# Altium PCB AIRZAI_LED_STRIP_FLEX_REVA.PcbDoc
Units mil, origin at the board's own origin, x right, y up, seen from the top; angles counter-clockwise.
Board outline 6238.19 x 814.96 mil, 2 copper layers (Top Layer, Bottom Layer); 59 components, 60 nets, 298 pads, 62 vias.
Unrouted connection lines stored in the file: 83.
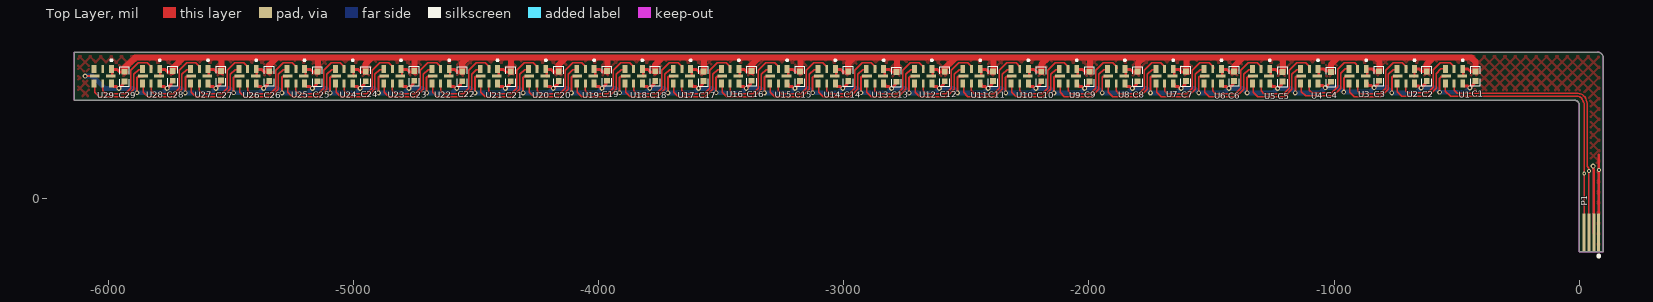
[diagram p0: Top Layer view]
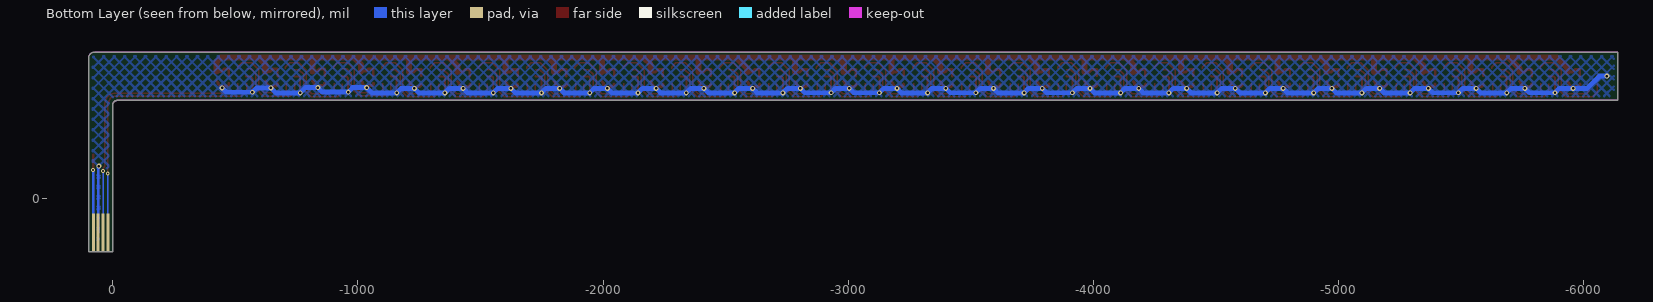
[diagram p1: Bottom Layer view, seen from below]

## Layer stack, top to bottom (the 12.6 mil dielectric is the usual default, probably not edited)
Top Solder: solder mask 0.4, Solder Resist, Dk 3.5
Top Layer: signal copper 1.4
Dielectric 1: dielectric 12.6, FR-4, Dk 4.8
Bottom Layer: signal copper 1.4
Bottom Solder: solder mask 0.4, Solder Resist, Dk 3.5

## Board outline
-6139.76,401 -6139.76,597.85 73.39,597.85 cw(c73.39,572.81) 98.43,572.81 98.43,-217.11 0,-217.11 0,381.31 ccw(c-19.69,381.31) -19.69,401
board region "Layer Stack Region 1": 98.43,43 98.43,-217.11 0,-217.11 0,43
board region "Layer Stack Region 1": 0,75 0,381.31 -0.38,385.16 -3.32,392.25 -8.75,397.68 -15.84,400.62 -19.69,401 -6139.76,401 -6139.76,597.85 73.39,597.85 78.37,597.85 87.57,594.04 94.61,586.99 98.43,577.79 98.43,572.81 98.43,75
board region "Layer Stack Region 2": 0,43 0,75 98.43,75 98.43,43

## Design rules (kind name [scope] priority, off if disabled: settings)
Clearance Clearance_polygon_5V [OnLayer('Keep-Out Layer') vs (InNet('+5V') AND InPolygon)] p1: gap=10 ignorepadtopadclearanceinfootprint=FALSE
Clearance Clearance_POLYGON_KEEPOUT [(OnLayer('Keep-Out Layer')) vs (InNet('GND') AND InPolygon)] p2: gap=10 ignorepadtopadclearanceinfootprint=FALSE
Clearance [All] p3: gap=6 ignorepadtopadclearanceinfootprint=FALSE
MinimumSolderMaskSliver [All] p1: minsoldermaskwidth=1
PolygonConnect [All] p1: connectstyle=Direct reliefconductorwidth=10 reliefentries=4 polygonreliefangle="90 Angle" airgapwidth=10
RoomDefinition AIRZAI_LED_STRIP_FLEX_REVA [InComponentClass('AIRZAI_LED_STRIP_FLEX_REVA')] p1: confinementstyle=ConfineIn formatcopy=TRUE lockcomponents=FALSE outline -10323.91,-4725.44 4336.09,-4725.44 4336.09,4874.56 -10323.91,4874.56
RoutingVias [All] p1: holewidth=28 width=50 viastyle="Through Hole" minholewidth=8 minwidth=16 maxholewidth=28 maxwidth=50
SilkToSilkClearance [All] p1: silktosilkclearance=1
SilkToSolderMaskClearance [IsPad] p1: minsilkscreentomaskgap=2 clearancetoexposedcopper=TRUE
SolderMaskExpansion [All] p1: expansion=4
UnRoutedNet [All] p1: checkbadconnections=TRUE
Width [All] p1: maxlimit=100 minlimit=6 preferedwidth=10
26 further rules are at their usual default settings.

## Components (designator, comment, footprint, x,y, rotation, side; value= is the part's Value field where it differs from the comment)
C1 "0.1µF" 0402CAP -423.76,499.43 r270 top
C2 "0.1µF" 0402CAP -622.6,499.43 r270 top
C3 "0.1µF" 0402CAP -817.46,500.11 r270 top
C4 "0.1µF" 0402CAP -1012.82,496.43 r270 top
C5 "0.1µF" 0402CAP -1210.17,497.11 r270 top
C6 "0.1µF" 0402CAP -1408.02,499.43 r270 top
C7 "0.1µF" 0402CAP -1604.87,499.11 r270 top
C8 "0.1µF" 0402CAP -1801.72,498.46 r270 top
C9 "0.1µF" 0402CAP -1997.57,497.93 r270 top
C10 "0.1µF" 0402CAP -2194.42,498.11 r270 top
C11 "0.1µF" 0402CAP -2391.59,499.11 r270 top
C12 "0.1µF" 0402CAP -2588.12,498.61 r270 top
C13 "0.1µF" 0402CAP -2784.97,496.42 r270 top
C14 "0.1µF" 0402CAP -2982.33,499.11 r270 top
C15 "0.1µF" 0402CAP -3178.76,499.11 r270 top
C16 "0.1µF" 0402CAP -3376.15,500.64 r270 top
C17 "0.1µF" 0402CAP -3572.37,499.11 r270 top
C18 "0.1µF" 0402CAP -3769.22,499.64 r270 top
C19 "0.1µF" 0402CAP -3965.64,500.58 r270 top
C20 "0.1µF" 0402CAP -4162.92,499.11 r270 top
C21 "0.1µF" 0402CAP -4358.77,498.63 r270 top
C22 "0.1µF" 0402CAP -4556.37,498.74 r270 top
C23 "0.1µF" 0402CAP -4752.47,500.58 r270 top
C24 "0.1µF" 0402CAP -4950.32,498.58 r270 top
C25 "0.1µF" 0402CAP -5146.9,498.9 r270 top
C26 "0.1µF" 0402CAP -5343.7,499.65 r270 top
C27 "0.1µF" 0402CAP -5540.44,500.95 r270 top
C28 "0.1µF" 0402CAP -5737.05,500.43 r270 top
C29 "0.1µF" 0402CAP -5934.14,497.46 r270 top
P1 "Header 4" FFC_4Pads 49.21,-138.39 r0 top
U1 "APA102-2020-256-8" APA102–2020 -510.76,499.43 r270 top
U2 "APA102-2020-256-8" APA102–2020 -707.76,499.43 r270 top
U3 "APA102-2020-256-8" APA102–2020 -904.46,499.43 r270 top
U4 "APA102-2020-256-8" APA102–2020 -1101.32,499.43 r270 top
U5 "APA102-2020-256-8" APA102–2020 -1298.17,499.43 r270 top
U6 "APA102-2020-256-8" APA102–2020 -1495.02,499.43 r270 top
U7 "APA102-2020-256-8" APA102–2020 -1691.87,499.43 r270 top
U8 "APA102-2020-256-8" APA102–2020 -1888.72,499.43 r270 top
U9 "APA102-2020-256-8" APA102–2020 -2085.57,499.43 r270 top
U10 "APA102-2020-256-8" APA102–2020 -2282.42,499.43 r270 top
U11 "APA102-2020-256-8" APA102–2020 -2479.27,499.43 r270 top
U12 "APA102-2020-256-8" APA102–2020 -2676.12,499.43 r270 top
U13 "APA102-2020-256-8" APA102–2020 -2872.97,499.43 r270 top
U14 "APA102-2020-256-8" APA102–2020 -3069.76,499.43 r270 top
U15 "APA102-2020-256-8" APA102–2020 -3266.76,499.43 r270 top
U16 "APA102-2020-256-8" APA102–2020 -3463.52,499.43 r270 top
U17 "APA102-2020-256-8" APA102–2020 -3660.37,499.43 r270 top
U18 "APA102-2020-256-8" APA102–2020 -3857.22,499.43 r270 top
U19 "APA102-2020-256-8" APA102–2020 -4054.07,499.43 r270 top
U20 "APA102-2020-256-8" APA102–2020 -4250.92,499.43 r270 top
U21 "APA102-2020-256-8" APA102–2020 -4447.77,499.43 r270 top
U22 "APA102-2020-256-8" APA102–2020 -4644.62,499.43 r270 top
U23 "APA102-2020-256-8" APA102–2020 -4841.47,499.43 r270 top
U24 "APA102-2020-256-8" APA102–2020 -5038.32,499.43 r270 top
U25 "APA102-2020-256-8" APA102–2020 -5235.17,499.43 r270 top
U26 "APA102-2020-256-8" APA102–2020 -5432.02,499.43 r270 top
U27 "APA102-2020-256-8" APA102–2020 -5628.87,499.43 r270 top
U28 "APA102-2020-256-8" APA102–2020 -5825.72,499.43 r270 top
U29 "APA102-2020-256-8" APA102–2020 -6022.57,499.43 r270 top

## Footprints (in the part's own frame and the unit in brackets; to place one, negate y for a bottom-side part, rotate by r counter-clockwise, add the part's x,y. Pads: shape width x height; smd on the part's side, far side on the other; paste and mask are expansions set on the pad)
0402CAP [mm] "Chip Capacitor, Body 1.1x0.5mm, IPC High Density"
  rect 0.6x0.6 smd: 1(-0.5,0) 2(0.5,0)
  silkscreen extent -1.02,-0.51 1.02,0.51, body extent -0.5,-0.3 0.5,0.3, height 0.19
APA102–2020 [mm]
  rect 0.8x0.5 smd: 1(-0.75,0.9) 3(-0.75,-0.9) 4(0.75,-0.9) 6(0.75,0.9)
  rect 0.8x0.3 smd: 2(-0.75,0) 5(0.75,0)
  rect 0.3x1 smd: 7(0,-0.83) 8(0,0.83)
  silkscreen extent -1.7,0.85 -1.6,0.95, body extent -1,-1 1,1, height 0.94
FFC_4Pads [mm] "(0.50mm"
  rect 0.3x4 smd: 1(0.75,0) 2(0.25,0) 3(-0.25,0) 4(-0.75,0)
  rect 0.3x4 smd far side: 1(0.75,0) 2(0.25,0) 3(-0.25,0) 4(-0.75,0)
  silkscreen extent 0.64,-2.56 0.89,-2.31

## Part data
C1 C2 C3 C4 C5 C6 C7 C8 C9 C10 C11 C12 C13 C14 C15 C16 C17 C18 C19 C20 C21 C22 C23 C24 C25 C26 C27 C28 C29: library part C0402-100n, "Capacitor, X7R, ±10%", Case-EIA=0402, Case-Metric=1005, Manufacturer=TDK, Manufacturer Part Number=C1005X7R1C104K, Rated Voltage="16 V", Supplier Part Number 1=445-4952-2-ND, Tolerance=±20%
P1: "Header, 4-Pin"
U1 U2 U3 U4 U5 U6 U7 U8 U9 U10 U11 U12 U13 U14 U15 U16 U17 U18 U19 U20 U21 U22 U23 U24 U25 U26 U27 U28 U29: "DotStar Micro LEDs", Package="SOIC-20 Adafruit Industries"

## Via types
v1: diameter 20, hole 10, Top Layer to Bottom Layer, tented both sides, 59 vias
v2: diameter 16, hole 8, Top Layer to Bottom Layer, tented both sides, 3 vias

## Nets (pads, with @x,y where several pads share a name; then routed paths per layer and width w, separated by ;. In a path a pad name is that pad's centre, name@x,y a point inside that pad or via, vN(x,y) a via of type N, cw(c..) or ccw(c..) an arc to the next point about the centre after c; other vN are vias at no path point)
+5V: C1.1 C2.1 C3.1 C4.1 C5.1 C6.1 C7.1 C8.1 C9.1 C10.1 C11.1 C12.1 C13.1 C14.1 C15.1 C16.1 C17.1 C18.1 C19.1 C20.1 C21.1 C22.1 C23.1 C24.1 C25.1 C26.1 C27.1 C28.1 C29.1 P1.1 U1.1 U1.8 U2.1 U2.8 U3.1 U3.8 U4.1 U4.8 U5.1 U5.8 U6.1 U6.8 U7.1 U7.8 U8.1 U8.8 U9.1 U9.8 U10.1 U10.8 U11.1 U11.8 U12.1 U12.8 U13.1 U13.8 U14.1 U14.8 U15.1 U15.8 U16.1 U16.8 U17.1 U17.8 U18.1 U18.8 U19.1 U19.8 U20.1 U20.8 U21.1 U21.8 U22.1 U22.8 U23.1 U23.8 U24.1 U24.8 U25.1 U25.8 U26.1 U26.8 U27.1 U27.8 U28.1 U28.8 U29.1 U29.8 | length 10646.1
  Top Layer w10: U29.8@-5984.3,499.43 U29.1@-5984.3,526.64 ; U28.8@-5787.45,499.43 U28.1@-5787.45,526.64 ; U27.8@-5589.52,501 U27.1@-5589.52,526.64 ; U26.8@-5393.75,499.43 U26.1@-5393.75,526.64 ; U25.8@-5195.82,501 U25.1@-5195.82,526.64 ; U24.8@-5000.05,499.43 U24.1@-5000.05,526.64 ; U23.8@-4802.12,501 U23.1@-4802.12,526.64 ; U22.8@-4606.35,499.43 U22.1@-4606.35,526.64 ; U21.8@-4408.42,501 U21.1@-4408.42,526.64 ; U20.8@-4212.64,499.43 U20.1@-4212.64,526.64 ; U19.8@-4014.72,501 U19.1@-4014.72,526.64 ; U18.8@-3818.94,499.43 U18.1@-3818.94,526.64 ; U17.8@-3621.01,501 U17.1@-3621.01,526.64 ; U16.8@-3425.34,499.43 U16.1@-3425.34,526.64 ; U15.8@-3227.41,501 U15.1@-3227.41,526.64 ; U14.8@-3031.54,499.43 U14.1@-3031.54,526.64 ; U13.8@-2833.61,501 U13.1@-2833.61,526.64 ; U12.8@-2637.84,499.43 U12.1@-2637.84,526.64 ; U11.8@-2439.91,501 U11.1@-2439.91,526.64 ; U10.8@-2244.14,499.43 U10.1@-2244.14,526.64 ; U9.8@-2046.21,501 U9.1@-2046.21,526.64 ; U8.8@-1850.44,499.43 U8.1@-1850.44,526.64 ; U7.8@-1652.51,501 U7.1@-1652.51,526.64 ; U6.8@-1456.74,499.43 U6.1@-1456.74,526.64 ; U5.8@-1258.81,501 U5.1@-1258.81,526.64 ; U4.8@-1065.79,500.12 -1063.94,500.12 -1063.04,501.02 U4.1@-1063.04,529.64 ; U3.8@-865.11,500.12 -864.2,501.02 U3.1@-864.2,529.64 ; U2.8 -673.24,499.43 -672.33,500.33 U2.1 ; U1.8@-474.4,499.43 -473.5,500.33 U1.1@-473.5,528.95 ; P1.1@78.74,-138.39 78.74,111.5 78.85,111.61 78.85,115.85 v2(80,117) 80,180
  Top Layer w12: U29.1@-5984.3,526.64 -5964.65,526.64 -5954.81,516.8 C29.1@-5934.57,516.8 ; U28.1@-5787.45,526.64 -5767.8,526.64 -5757.96,516.8 C28.1@-5737.72,516.8 ; U27.1@-5589.52,526.64 -5568.97,526.64 -5559.12,516.8 C27.1@-5538.88,516.8 ; U26.1@-5393.75,526.64 -5374.1,526.64 -5364.26,516.8 C26.1@-5344.01,516.8 ; U25.1@-5195.82,526.64 -5175.27,526.64 -5165.42,516.8 C25.1@-5145.18,516.8 ; U24.1@-5000.05,526.64 -4980.4,526.64 -4970.56,516.8 C24.1@-4950.31,516.8 ; U23.1@-4802.12,526.64 -4781.57,526.64 -4771.72,516.8 C23.1@-4751.48,516.8 ; U22.1@-4606.35,526.64 -4586.7,526.64 -4576.86,516.8 C22.1@-4556.61,516.8 ; U21.1@-4408.42,526.64 -4387.86,526.64 -4378.02,516.8 C21.1@-4357.78,516.8 ; U20.1@-4212.64,526.64 -4193,526.64 -4183.16,516.8 C20.1@-4162.91,516.8 ; U19.1@-4014.72,526.64 -3994.16,526.64 -3984.32,516.8 C19.1@-3964.08,516.8 ; U18.1@-3818.94,526.64 -3799.3,526.64 -3789.46,516.8 C18.1@-3769.21,516.8 ; U17.1@-3621.01,526.64 -3600.46,526.64 -3590.62,516.8 C17.1@-3570.38,516.8 ; U16.1@-3425.34,526.64 -3405.69,526.64 -3395.85,516.8 C16.1@-3375.6,516.8 ; U15.1@-3227.41,526.64 -3206.86,526.64 -3197.01,516.8 C15.1@-3176.77,516.8 ; U14.1@-3031.54,526.64 -3011.9,526.64 -3002.05,516.8 C14.1@-2981.81,516.8 ; U13.1@-2833.61,526.64 -2813.06,526.64 -2803.22,516.8 C13.1@-2782.97,516.8 ; U12.1@-2637.84,526.64 -2618.19,526.64 -2608.35,516.8 C12.1@-2588.11,516.8 ; U11.1@-2439.91,526.64 -2419.36,526.64 -2409.52,516.8 C11.1@-2389.27,516.8 ; U10.1@-2244.14,526.64 -2224.49,526.64 -2214.65,516.8 C10.1@-2194.41,516.8 ; U9.1@-2046.21,526.64 -2025.66,526.64 -2015.82,516.8 C9.1@-1995.57,516.8 ; U8.1@-1850.44,526.64 -1830.79,526.64 -1820.95,516.8 C8.1@-1800.71,516.8 ; U7.1@-1652.51,526.64 -1631.96,526.64 -1622.12,516.8 C7.1@-1601.87,516.8 ; U6.1@-1456.74,526.64 -1437.09,526.64 -1427.25,516.8 C6.1@-1407.01,516.8 ; U5.1@-1258.81,526.64 -1238.26,526.64 -1228.42,516.8 C5.1@-1208.17,516.8 ; U4.1@-1063.04,529.64 -1043.39,529.64 -1033.55,519.8 C4.1@-1013.31,519.8 ; U3.1@-864.2,529.64 -844.56,529.64 -834.72,519.8 C3.1@-814.47,519.8 ; U2.1 -652.69,528.95 -642.84,519.11 C2.1 ; U1.1@-473.5,528.95 -453.85,528.95 -444.01,519.11 C1.1
  Top Layer w25: C29.1@-5934.57,516.8 -5934.57,530.99 -5890.36,575.2 -5667,575.2 ; C28.1@-5737.72,516.8 -5737.72,530.99 -5693.51,575.2 -5667,575.2 ; C27.1@-5538.88,516.8 -5538.88,568.88 -5545.2,575.2 ; C26.1@-5344.01,516.8 -5344.01,544.84 -5313.66,575.2 ; C25.1@-5145.18,516.8 -5145.18,573.18 -5147.2,575.2 ; C24.1@-4950.31,516.8 -4950.31,549.39 -4924.5,575.2 ; -4758.42,575.2 -4751.48,568.26 C23.1@-4751.48,516.8 ; C22.1@-4556.61,516.8 -4556.61,552.09 -4533.5,575.2 -4530.8,575.2 ; C21.1@-4357.78,516.8 -4357.78,572.56 -4360.42,575.2 ; C20.1@-4162.91,516.8 -4162.91,545.69 -4133.4,575.2 ; C19.1@-3964.08,516.8 -3964.08,571.48 -3967.8,575.2 ; C18.1@-3769.21,516.8 -3769.21,545.79 -3739.8,575.2 ; C17.1@-3570.38,516.8 -3570.38,569.38 -3576.2,575.2 ; C16.1@-3375.6,516.8 -3375.6,546.1 -3346.51,575.2 ; C15.1@-3176.77,516.8 -3176.77,569.77 -3182.2,575.2 ; C14.1@-2981.81,516.8 -2981.81,553.19 -2959.8,575.2 ; C13.1@-2782.97,516.8 -2782.97,572.97 -2785.2,575.2 ; C12.1@-2588.11,516.8 -2588.11,530.99 -2543.9,575.2 ; -2396.47,575.2 -2389.27,568 C11.1@-2389.27,516.8 ; C10.1@-2194.41,516.8 -2194.41,547.17 -2166.37,575.2 ; C9.1@-1995.57,516.8 -1995.57,575.2 ; C8.1@-1800.71,516.8 -1800.71,551.29 -1776.8,575.2 -1688.87,575.2 ; C7.1@-1601.87,516.8 -1601.87,569.87 -1607.2,575.2 -1688.87,575.2 ; C6.1@-1407.01,516.8 -1407.01,539.99 -1371.8,575.2 -1245,575.2 ; C5.1@-1208.17,516.8 -1208.17,575.2 -1245,575.2 ; C4.1@-1013.31,519.8 -1013.31,546.77 -989.43,570.64 ; C3.1@-814.47,519.8 -814.47,559.45 -830.22,575.2 ; C2.1 -622.6,547.22 -595.41,574.41 -596.2,575.2 ; C1.1 -423.76,558.76 -440.2,575.2 -596.2,575.2 ; -5667,575.2 -5545.2,575.2 ; -5545.2,575.2 -5313.66,575.2 ; -5313.66,575.2 -5147.2,575.2 ; -5147.2,575.2 -4530.8,575.2 ; -4530.8,575.2 -4360.42,575.2 ; -4360.42,575.2 -4133.4,575.2 ; -4133.4,575.2 -3967.8,575.2 ; -3967.8,575.2 -3739.8,575.2 ; -3739.8,575.2 -3576.2,575.2 ; -3576.2,575.2 -3346.51,575.2 ; -3346.51,575.2 -3182.2,575.2 ; -3182.2,575.2 -2959.8,575.2 ; -2959.8,575.2 -2907,575.2 -2785.2,575.2 ; -2785.2,575.2 -2543.9,575.2 ; -2543.9,575.2 -2166.37,575.2 ; -2166.37,575.2 -1995.57,575.2 ; -1995.57,575.2 -1688.87,575.2 ; -1688.87,575.2 -1245,575.2 ; -1245,575.2 -830.22,575.2 ; -830.22,575.2 -596.2,575.2
  Bottom Layer w10: P1.1@78.74,-138.39 78.74,111.5 78.85,111.61 78.85,115.63 78.74,115.74 v2(80,117)
GND: C1.2 C2.2 C3.2 C4.2 C5.2 C6.2 C7.2 C8.2 C9.2 C10.2 C11.2 C12.2 C13.2 C14.2 C15.2 C16.2 C17.2 C18.2 C19.2 C20.2 C21.2 C22.2 C23.2 C24.2 C25.2 C26.2 C27.2 C28.2 C29.2 P1.2 U1.6 U1.7 U2.6 U2.7 U3.6 U3.7 U4.6 U4.7 U5.6 U5.7 U6.6 U6.7 U7.6 U7.7 U8.6 U8.7 U9.6 U9.7 U10.6 U10.7 U11.6 U11.7 U12.6 U12.7 U13.6 U13.7 U14.6 U14.7 U15.6 U15.7 U16.6 U16.7 U17.6 U17.7 U18.6 U18.7 U19.6 U19.7 U20.6 U20.7 U21.6 U21.7 U22.6 U22.7 U23.6 U23.7 U24.6 U24.7 U25.6 U25.7 U26.6 U26.7 U27.6 U27.7 U28.6 U28.7 U29.6 U29.7 | length 11347.9
  Top Layer w8: v1(-6095,499.43) U29.7 ; v1(-5882.97,431.69) -5882.97,494.59 -5880.04,497.52 -5860.31,497.52 U28.7 ; v1(-5686.12,431.69) -5686.12,494.59 -5683.19,497.52 -5663.46,497.52 U27.7 ; v1(-5489.27,431.69) -5489.27,494.59 -5486.34,497.52 -5466.61,497.52 U26.7 ; v1(-5292.42,431.69) -5292.42,494.59 -5289.49,497.52 -5269.76,497.52 U25.7 ; v1(-5095.57,431.69) -5095.57,494.59 -5092.64,497.52 -5072.91,497.52 U24.7 ; v1(-4898.72,431.69) -4898.72,494.59 -4895.79,497.52 -4876.06,497.52 U23.7 ; v1(-4701.86,431.69) -4701.86,494.59 -4698.94,497.52 -4679.2,497.52 U22.7 ; v1(-4505.01,431.69) -4505.01,494.59 -4502.09,497.52 -4482.35,497.52 U21.7 ; v1(-4308.16,431.69) -4308.16,494.59 -4305.24,497.52 -4285.5,497.52 U20.7 ; v1(-4111.31,431.69) -4111.31,494.59 -4108.39,497.52 -4088.65,497.52 U19.7 ; v1(-3914.46,431.69) -3914.46,494.59 -3911.53,497.52 -3891.8,497.52 U18.7 ; v1(-3717.61,431.69) -3717.61,494.59 -3714.68,497.52 -3694.95,497.52 U17.7 ; v1(-3520.76,431.69) -3520.76,494.59 -3517.83,497.52 -3498.1,497.52 U16.7 ; v1(-3324.01,431.69) -3324.01,494.59 -3321.08,497.52 -3301.35,497.52 U15.7 ; v1(-3127.01,431.69) -3127.01,494.59 -3124.08,497.52 -3104.35,497.52 U14.7 ; v1(-2930.21,431.69) -2930.21,494.59 -2927.28,497.52 -2907.55,497.52 U13.7 ; v1(-2733.36,431.69) -2733.36,494.59 -2730.43,497.52 -2710.7,497.52 U12.7 ; v1(-2536.51,431.69) -2536.51,494.59 -2533.58,497.52 -2513.85,497.52 U11.7 ; v1(-2339.66,431.69) -2339.66,494.59 -2336.73,497.52 -2317,497.52 U10.7 ; v1(-2142.81,431.69) -2142.81,494.59 -2139.88,497.52 -2120.15,497.52 U9.7 ; v1(-1945.96,431.69) -1945.96,494.59 -1943.03,497.52 -1923.3,497.52 U8.7 ; v1(-1749.11,431.69) -1749.11,494.59 -1746.18,497.52 -1726.45,497.52 U7.7 ; v1(-1552.26,431.69) -1552.26,494.59 -1549.33,497.52 -1529.6,497.52 U6.7 ; v1(-1355.41,431.69) -1355.41,494.59 -1352.48,497.52 -1332.75,497.52 U5.7 ; v1(-1158.56,431.69) -1158.56,494.59 -1155.63,497.52 -1135.9,497.52 U4.7 ; v1(-960.71,434.69) -960.71,491.69 -954.88,497.52 -939.05,497.52 U3.7 ; U3.7@-936.05,498.21 U3.7@-934.15,500.12 ; v1(-765.01,431.69) -765.01,494.59 -762.08,497.52 -742.35,497.52 U2.7 ; v1(-570,434) -570,491 -563.48,497.52 -545.35,497.52 U1.7
  Top Layer w10: v1@57.91,131.09 v1(56,133) 56,123 59.06,119.94 P1.2@59.06,-138.39
  Top Layer w12: U29.6@-5984.3,467.59 -5984.3,461.68 -5980.45,457.84 -5967.28,457.84 -5959.13,449.69 v1(-5956.97,449.69) -5940.38,466.28 -5940.38,471.62 C29.2@-5934.57,477.43 ; U28.6@-5787.45,467.59 -5787.45,461.68 -5783.61,457.84 -5770.43,457.84 -5762.28,449.69 v1(-5760.12,449.69) -5743.53,466.28 -5743.53,471.62 C28.2@-5737.72,477.43 ; U27.6@-5588.61,467.59 -5588.61,461.68 -5584.77,457.84 -5571.6,457.84 -5563.45,449.69 v1(-5561.28,449.69) -5544.69,466.28 -5544.69,471.62 C27.2@-5538.88,477.43 ; U26.6@-5393.75,467.59 -5393.75,461.68 -5389.9,457.84 -5376.73,457.84 -5368.58,449.69 v1(-5366.42,449.69) -5349.83,466.28 -5349.83,471.62 C26.2@-5344.01,477.43 ; U25.6@-5194.91,467.59 -5194.91,461.68 -5191.07,457.84 -5177.9,457.84 -5169.75,449.69 v1(-5167.58,449.69) -5150.99,466.28 -5150.99,471.62 C25.2@-5145.18,477.43 ; U24.6@-5000.05,467.59 -5000.05,461.68 -4996.2,457.84 -4983.03,457.84 -4974.88,449.69 v1(-4972.72,449.69) -4956.12,466.28 -4956.12,471.62 C24.2@-4950.31,477.43 ; U23.6@-4801.21,467.59 -4801.21,461.68 -4797.37,457.84 -4784.19,457.84 -4776.05,449.69 v1(-4773.88,449.69) -4757.29,466.28 -4757.29,471.62 C23.2@-4751.48,477.43 ; U22.6@-4606.35,467.59 -4606.35,461.68 -4602.5,457.84 -4589.33,457.84 -4581.18,449.69 v1(-4579.01,449.69) -4562.42,466.28 -4562.42,471.62 C22.2@-4556.61,477.43 ; U21.6@-4407.51,467.59 -4407.51,461.68 -4403.67,457.84 -4390.49,457.84 -4382.34,449.69 v1(-4380.18,449.69) -4363.59,466.28 -4363.59,471.62 C21.2@-4357.78,477.43 ; U20.6@-4212.64,467.59 -4212.64,461.68 -4208.8,457.84 -4195.63,457.84 -4187.48,449.69 v1(-4185.31,449.69) -4168.72,466.28 -4168.72,471.62 C20.2@-4162.91,477.43 ; U19.6@-4013.81,467.59 -4013.81,461.68 -4009.97,457.84 -3996.79,457.84 -3988.64,449.69 v1(-3986.48,449.69) -3969.89,466.28 -3969.89,471.62 C19.2@-3964.08,477.43 ; U18.6@-3818.94,467.59 -3818.94,461.68 -3815.1,457.84 -3801.93,457.84 -3793.78,449.69 v1(-3791.61,449.69) -3775.02,466.28 -3775.02,471.62 C18.2@-3769.21,477.43 ; U17.6@-3620.11,467.59 -3620.11,461.68 -3616.27,457.84 -3603.09,457.84 -3594.94,449.69 v1(-3592.78,449.69) -3576.19,466.28 -3576.19,471.62 C17.2@-3570.38,477.43 ; U16.6@-3425.34,467.59 -3425.34,461.68 -3421.49,457.84 -3408.32,457.84 -3400.17,449.69 v1(-3398.01,449.69) -3381.42,466.28 -3381.42,471.62 C16.2@-3375.6,477.43 ; U15.6@-3226.5,467.59 -3226.5,461.68 -3222.66,457.84 -3209.49,457.84 -3201.34,449.69 v1(-3199.17,449.69) -3182.58,466.28 -3182.58,471.62 C15.2@-3176.77,477.43 ; U14.6@-3031.54,467.59 -3031.54,461.68 -3027.7,457.84 -3014.52,457.84 -3006.37,449.69 v1(-3004.21,449.69) -2987.62,466.28 -2987.62,471.62 C14.2@-2981.81,477.43 ; U13.6@-2832.71,467.59 -2832.71,461.68 -2828.86,457.84 -2815.69,457.84 -2807.54,449.69 v1(-2805.38,449.69) -2788.78,466.28 -2788.78,471.62 C13.2@-2782.97,477.43 ; U12.6@-2637.84,467.59 -2637.84,461.68 -2634,457.84 -2620.82,457.84 -2612.67,449.69 v1(-2610.51,449.69) -2593.92,466.28 -2593.92,471.62 C12.2@-2588.11,477.43 ; U11.6@-2439.01,467.59 -2439.01,461.68 -2435.16,457.84 -2421.99,457.84 -2413.84,449.69 v1(-2411.68,449.69) -2395.08,466.28 -2395.08,471.62 C11.2@-2389.27,477.43 ; U10.6@-2244.14,467.59 -2244.14,461.68 -2240.3,457.84 -2227.12,457.84 -2218.97,449.69 v1(-2216.81,449.69) -2200.22,466.28 -2200.22,471.62 C10.2@-2194.41,477.43 ; U9.6@-2045.3,467.59 -2045.3,461.68 -2041.46,457.84 -2028.29,457.84 -2020.14,449.69 v1(-2017.97,449.69) -2001.38,466.28 -2001.38,471.62 C9.2@-1995.57,477.43 ; U8.6@-1850.44,467.59 -1850.44,461.68 -1846.6,457.84 -1833.42,457.84 -1825.27,449.69 v1(-1823.11,449.69) -1806.52,466.28 -1806.52,471.62 C8.2@-1800.71,477.43 ; U7.6@-1651.6,467.59 -1651.6,461.68 -1647.76,457.84 -1634.59,457.84 -1626.44,449.69 v1(-1624.27,449.69) -1607.68,466.28 -1607.68,471.62 C7.2@-1601.87,477.43 ; U6.6@-1456.74,467.59 -1456.74,461.68 -1452.9,457.84 -1439.72,457.84 -1431.57,449.69 v1(-1429.41,449.69) -1412.82,466.28 -1412.82,471.62 C6.2@-1407.01,477.43 ; U5.6@-1257.9,467.59 -1257.9,461.68 -1254.06,457.84 -1240.89,457.84 -1232.74,449.69 v1(-1230.57,449.69) -1213.98,466.28 -1213.98,471.62 C5.2@-1208.17,477.43 ; U4.6@-1063.04,470.59 -1063.04,464.68 -1059.2,460.84 -1046.02,460.84 -1037.87,452.69 v1(-1035.71,452.69) -1019.12,469.28 -1019.12,474.62 C4.2@-1013.31,480.43 ; U3.6@-864.2,470.59 -864.2,464.68 -860.36,460.84 -847.19,460.84 -839.04,452.69 v1(-836.87,452.69) -820.28,469.28 -820.28,474.62 C3.2@-814.47,480.43 ; U2.6 -672.33,463.99 -668.49,460.15 -655.31,460.15 -647.16,452 v1(-645,452) -628.41,468.59 -628.41,473.93 C2.2 ; U1.6@-473.5,469.9 -473.5,463.99 -469.65,460.15 -456.48,460.15 -448.33,452 v1(-446.17,452) -429.57,468.59 -429.57,473.93 C1.2
  Bottom Layer w10: P1.2@59.06,-138.39 59.06,122.87
  Bottom Layer w20: v1(-6095,499.43) -6064.43,499.43 -6014.69,449.69 v1(-5956.97,449.69) -5900.97,449.69 v1(-5882.97,431.69) -5778.12,431.69 v1(-5760.12,449.69) -5704.12,449.69 v1(-5686.12,431.69) -5579.28,431.69 v1(-5561.28,449.69) -5507.26,449.69 v1(-5489.27,431.69) -5384.42,431.69 v1(-5366.42,449.69) -5310.42,449.69 v1(-5292.42,431.69) -5185.58,431.69 v1(-5167.58,449.69) -5113.57,449.69 v1(-5095.57,431.69) -4990.72,431.69 v1(-4972.72,449.69) -4916.72,449.69 v1(-4898.72,431.69) -4791.88,431.69 v1(-4773.88,449.69) -4719.86,449.69 v1(-4701.86,431.69) -4597.01,431.69 v1(-4579.01,449.69) -4523.01,449.69 v1(-4505.01,431.69) -4398.18,431.69 v1(-4380.18,449.69) -4326.16,449.69 v1(-4308.16,431.69) -4203.31,431.69 v1(-4185.31,449.69) -4129.31,449.69 v1(-4111.31,431.69) -4004.48,431.69 v1(-3986.48,449.69) -3932.46,449.69 v1(-3914.46,431.69) -3809.61,431.69 v1(-3791.61,449.69) -3735.61,449.69 v1(-3717.61,431.69) -3610.78,431.69 v1(-3592.78,449.69) -3538.76,449.69 v1(-3520.76,431.69) -3416.01,431.69 v1(-3398.01,449.69) -3342.01,449.69 v1(-3324.01,431.69) -3217.17,431.69 v1(-3199.17,449.69) -3145,449.69 v1(-3127.01,431.69) -3022.21,431.69 v1(-3004.21,449.69) -2948.21,449.69 v1(-2930.21,431.69) -2823.38,431.69 v1(-2805.38,449.69) -2751.36,449.69 v1(-2733.36,431.69) -2628.51,431.69 v1(-2610.51,449.69) -2554.51,449.69 v1(-2536.51,431.69) -2429.68,431.69 v1(-2411.68,449.69) -2357.66,449.69 v1(-2339.66,431.69) -2234.81,431.69 v1(-2216.81,449.69) -2160.81,449.69 v1(-2142.81,431.69) -2035.97,431.69 v1(-2017.97,449.69) -1963.96,449.69 v1(-1945.96,431.69) -1841.11,431.69 v1(-1823.11,449.69) -1767.11,449.69 v1(-1749.11,431.69) -1642.27,431.69 v1(-1624.27,449.69) -1570.26,449.69 v1(-1552.26,431.69) -1447.41,431.69 v1(-1429.41,449.69) -1373.41,449.69 v1(-1355.41,431.69) -1248.57,431.69 v1(-1230.57,449.69) -1176.56,449.69 v1(-1158.56,431.69) -1056.71,431.69 v1(-1035.71,452.69) -978.71,452.69 v1(-960.71,434.69) -854.87,434.69 v1(-836.87,452.69) -786.01,452.69 v1(-765.01,431.69) -665.31,431.69 v1(-645,452) -588,452 v1(-570,434) -464.17,434 v1(-446.17,452)
LED_CLK_IN: P1.3 U1.5 | length 1379.3
  Top Layer w6: U1.5 -510.76,441.76 -498,429 -4.73,429 cw(c-4.73,398.27) 17,420 cw(c-21.63,381.37) 33,381.37 33,134.66 ccw(c46.66,134.66) 37,125 cw(c31.28,119.28) 39.37,119.28 v2(39.37,113) P1.3@39.37,-138.39
  Bottom Layer w6: P1.3@39.37,-138.39 v2(39.37,113)
LED_CLK_OUT1: U1.2 U2.5 | length 339.5
  Top Layer w6: U2.5 -707.76,439.15 -699.61,431 -619,431 -595.5,454.5 -595.5,526.5 -568.3,553.7 -526.7,553.7 -510.76,537.76 U1.2
LED_CLK_OUT2: U2.2 U3.5 | length 342.6
  Top Layer w6: U3.5@-904.61,469.9 -904.61,439.68 -893.62,428.69 -813.01,428.69 -790.6,451.1 -790.6,523.1 -760,553.7 -723.02,553.7 -704.77,535.45 U2.2@-704.77,528.95
LED_CLK_OUT3: U3.2 U4.5 | length 339.5
  Top Layer w6: U4.5 -1101.32,442.68 -1090.32,431.69 -1009.71,431.69 -985.71,455.69 -985.71,527.69 -959.7,553.7 -916.72,553.7 -901.47,538.45 U3.2@-901.47,529.64
LED_CLK_OUT4: U4.2 U5.5 | length 342.6
  Top Layer w6: U5.5 -1298.17,439.68 -1287.17,428.69 -1206.56,428.69 -1184.15,451.1 -1184.15,523.1 -1153.55,553.7 -1116.57,553.7 -1098.32,535.45 U4.2@-1098.32,528.95
LED_CLK_OUT5: U5.2 U6.5 | length 342.6
  Top Layer w6: U6.5 -1495.02,439.68 -1484.02,428.69 -1403.41,428.69 -1381,451.1 -1381,523.1 -1350.4,553.7 -1313.42,553.7 -1295.17,535.45 U5.2@-1295.17,528.95
LED_CLK_OUT6: U6.2 U7.5 | length 342.6
  Top Layer w6: U7.5 -1691.87,439.68 -1680.87,428.69 -1600.26,428.69 -1577.85,451.1 -1577.85,523.1 -1547.25,553.7 -1510.27,553.7 -1492.02,535.45 U6.2@-1492.02,528.95
LED_CLK_OUT7: U7.2 U8.5 | length 342.6
  Top Layer w6: U8.5 -1888.72,439.68 -1877.72,428.69 -1797.11,428.69 -1774.7,451.1 -1774.7,523.1 -1744.1,553.7 -1707.12,553.7 -1688.87,535.45 U7.2@-1688.87,528.95
LED_CLK_OUT8: U8.2 U9.5 | length 342.6
  Top Layer w6: U9.5 -2085.57,439.68 -2074.57,428.69 -1993.96,428.69 -1971.55,451.1 -1971.55,523.1 -1940.95,553.7 -1903.97,553.7 -1885.72,535.45 U8.2@-1885.72,528.95
LED_CLK_OUT9: U9.2 U10.5 | length 342.6
  Top Layer w6: U10.5 -2282.42,439.68 -2271.42,428.69 -2190.81,428.69 -2168.4,451.1 -2168.4,523.1 -2137.8,553.7 -2100.82,553.7 -2082.57,535.45 U9.2@-2082.57,528.95
LED_CLK_OUT10: U10.2 U11.5 | length 342.6
  Top Layer w6: U11.5 -2479.27,439.68 -2468.27,428.69 -2387.66,428.69 -2365.25,451.1 -2365.25,523.1 -2334.65,553.7 -2297.67,553.7 -2279.42,535.45 U10.2@-2279.42,528.95
LED_CLK_OUT11: U11.2 U12.5 | length 342.6
  Top Layer w6: U12.5 -2676.12,439.68 -2665.12,428.69 -2584.51,428.69 -2562.1,451.1 -2562.1,523.1 -2531.5,553.7 -2494.52,553.7 -2476.27,535.45 U11.2@-2476.27,528.95
LED_CLK_OUT12: U12.2 U13.5 | length 342.6
  Top Layer w6: U13.5 -2872.97,439.68 -2861.97,428.69 -2781.36,428.69 -2758.95,451.1 -2758.95,523.1 -2728.35,553.7 -2691.37,553.7 -2673.12,535.45 U12.2@-2673.12,528.95
LED_CLK_OUT13: U13.2 U14.5 | length 342.6
  Top Layer w6: U14.5 -3069.82,439.68 -3058.82,428.69 -2978.21,428.69 -2955.8,451.1 -2955.8,523.1 -2925.2,553.7 -2888.22,553.7 -2869.97,535.45 U13.2@-2869.97,528.95
LED_CLK_OUT14: U14.2 U15.5 | length 342.6
  Top Layer w6: U15.5@-3266.61,469.9 -3266.61,439.68 -3255.62,428.69 -3175.01,428.69 -3152.6,451.1 -3152.6,523.1 -3121.99,553.7 -3085.02,553.7 -3066.77,535.45 U14.2@-3066.77,528.95
LED_CLK_OUT15: U15.2 U16.5 | length 342.6
  Top Layer w6: U16.5@-3463.61,469.9 -3463.61,439.68 -3452.62,428.69 -3372.01,428.69 -3349.6,451.1 -3349.6,523.1 -3319,553.7 -3282.02,553.7 -3263.77,535.45 U15.2@-3263.77,528.95
LED_CLK_OUT16: U16.2 U17.5 | length 342.6
  Top Layer w6: U17.5 -3660.37,439.68 -3649.38,428.69 -3568.76,428.69 -3546.35,451.1 -3546.35,523.1 -3515.75,553.7 -3478.77,553.7 -3460.53,535.45 U16.2@-3460.53,528.95
LED_CLK_OUT17: U17.2 U18.5 | length 342.6
  Top Layer w6: U18.5 -3857.22,439.68 -3846.23,428.69 -3765.61,428.69 -3743.2,451.1 -3743.2,523.1 -3712.6,553.7 -3675.62,553.7 -3657.38,535.45 U17.2@-3657.38,528.95
LED_CLK_OUT18: U18.2 U19.5 | length 342.6
  Top Layer w6: U19.5 -4054.07,439.68 -4043.08,428.69 -3962.46,428.69 -3940.05,451.1 -3940.05,523.1 -3909.45,553.7 -3872.47,553.7 -3854.23,535.45 U18.2@-3854.23,528.95
LED_CLK_OUT19: U19.2 U20.5 | length 342.6
  Top Layer w6: U20.5 -4250.92,439.68 -4239.93,428.69 -4159.31,428.69 -4136.91,451.1 -4136.91,523.1 -4106.3,553.7 -4069.32,553.7 -4051.08,535.45 U19.2@-4051.08,528.95
LED_CLK_OUT20: U20.2 U21.5 | length 342.6
  Top Layer w6: U21.5 -4447.77,439.68 -4436.78,428.69 -4356.16,428.69 -4333.76,451.1 -4333.76,523.1 -4303.15,553.7 -4266.17,553.7 -4247.93,535.45 U20.2@-4247.93,528.95
LED_CLK_OUT21: U21.2 U22.5 | length 342.6
  Top Layer w6: U22.5 -4644.62,439.68 -4633.63,428.69 -4553.01,428.69 -4530.61,451.1 -4530.61,523.1 -4500,553.7 -4463.03,553.7 -4444.78,535.45 U21.2@-4444.78,528.95
LED_CLK_OUT22: U22.2 U23.5 | length 342.6
  Top Layer w6: U23.5 -4841.47,439.68 -4830.48,428.69 -4749.86,428.69 -4727.46,451.1 -4727.46,523.1 -4696.85,553.7 -4659.88,553.7 -4641.63,535.45 U22.2@-4641.63,528.95
LED_CLK_OUT23: U23.2 U24.5 | length 342.6
  Top Layer w6: U24.5 -5038.32,439.68 -5027.33,428.69 -4946.72,428.69 -4924.31,451.1 -4924.31,523.1 -4893.7,553.7 -4856.73,553.7 -4838.48,535.45 U23.2@-4838.48,528.95
LED_CLK_OUT24: U24.3 U25.4 | length 319.5
  Top Layer w6: U25.4@-5267.76,467.59 -5267.76,433.89 -5249.57,415.69 -5139.57,415.69 -5109.16,446.1 -5109.16,506.42 -5088.94,526.64 U24.3@-5070.76,526.64
LED_CLK_OUT25: U25.2 U26.5 | length 342.6
  Top Layer w6: U26.5 -5432.02,439.68 -5421.03,428.69 -5340.42,428.69 -5318.01,451.1 -5318.01,523.1 -5287.41,553.7 -5250.43,553.7 -5232.18,535.45 U25.2@-5232.18,528.95
LED_CLK_OUT26: U26.2 U27.5 | length 342.6
  Top Layer w6: U27.5 -5628.87,439.68 -5617.88,428.69 -5537.27,428.69 -5514.86,451.1 -5514.86,523.1 -5484.26,553.7 -5447.28,553.7 -5429.03,535.45 U26.2@-5429.03,528.95
LED_CLK_OUT27: U27.2 U28.5 | length 342.6
  Top Layer w6: U28.5 -5825.72,439.68 -5814.73,428.69 -5734.12,428.69 -5711.71,451.1 -5711.71,523.1 -5681.11,553.7 -5644.13,553.7 -5625.88,535.45 U27.2@-5625.88,528.95
LED_CLK_OUT28: U28.2 U29.5 | length 342.6
  Top Layer w6: U29.5 -6022.57,439.68 -6011.58,428.69 -5930.97,428.69 -5908.56,451.1 -5908.56,523.1 -5877.96,553.7 -5840.98,553.7 -5822.73,535.45 U28.2@-5822.73,528.95
LED_SDI: P1.4 U1.4 | length 1388.6
  Top Layer w6: U1.4 -546.2,438.2 -525,417 -7.49,417 cw(c-7.49,396.51) 7,411 cw(c-23.62,380.38) 19.68,380.38 P1.4@19.68,-138.39
  Bottom Layer w6: P1.4@19.68,-138.39 20,-138.07 v2(20,102)
LED_SDO_1: U1.3 U2.4 | length 319.5
  Top Layer w6: U2.4 -743.2,436.2 -725,418 -615,418 -583,450 -583,510.32 -564.37,528.95 U1.3
LED_SDO_2: U2.3 U3.4 | length 319.5
  Top Layer w6: U3.4@-937.2,467.59 -937.2,433.89 -919.01,415.69 -809.01,415.69 -778.6,446.1 -778.6,506.42 -758.38,526.64 U2.3@-740.2,526.64
LED_SDO_3: U3.3 U4.4 | length 319.5
  Top Layer w6: U4.4@-1133.9,470.59 -1133.9,436.89 -1115.71,418.69 -1005.71,418.69 -973.71,450.69 -973.71,511.01 -955.08,529.64 U3.3@-936.9,529.64
LED_SDO_4: U4.3 U5.4 | length 319.5
  Top Layer w6: U5.4@-1330.75,467.59 -1330.75,433.89 -1312.56,415.69 -1202.56,415.69 -1172.15,446.1 -1172.15,506.42 -1151.93,526.64 U4.3@-1133.75,526.64
LED_SDO_5: U5.3 U6.4 | length 319.5
  Top Layer w6: U6.4@-1527.6,467.59 -1527.6,433.89 -1509.41,415.69 -1399.41,415.69 -1369,446.1 -1369,506.42 -1348.78,526.64 U5.3@-1330.6,526.64
LED_SDO_6: U6.3 U7.4 | length 319.5
  Top Layer w6: U7.4@-1724.46,467.59 -1724.46,433.89 -1706.26,415.69 -1596.26,415.69 -1565.85,446.1 -1565.85,506.42 -1545.63,526.64 U6.3@-1527.46,526.64
LED_SDO_7: U7.3 U8.4 | length 319.5
  Top Layer w6: U8.4@-1921.31,467.59 -1921.31,433.89 -1903.11,415.69 -1793.11,415.69 -1762.7,446.1 -1762.7,506.42 -1742.48,526.64 U7.3@-1724.31,526.64
LED_SDO_8: U8.3 U9.4 | length 319.5
  Top Layer w6: U9.4@-2118.16,467.59 -2118.16,433.89 -2099.96,415.69 -1989.96,415.69 -1959.55,446.1 -1959.55,506.42 -1939.33,526.64 U8.3@-1921.16,526.64
LED_SDO_9: U9.3 U10.4 | length 319.5
  Top Layer w6: U10.4@-2315.01,467.59 -2315.01,433.89 -2296.81,415.69 -2186.81,415.69 -2156.4,446.1 -2156.4,506.42 -2136.18,526.64 U9.3@-2118.01,526.64
LED_SDO_10: U10.3 U11.4 | length 319.5
  Top Layer w6: U11.4@-2511.86,467.59 -2511.86,433.89 -2493.66,415.69 -2383.66,415.69 -2353.25,446.1 -2353.25,506.42 -2333.03,526.64 U10.3@-2314.86,526.64
LED_SDO_11: U11.3 U12.4 | length 319.5
  Top Layer w6: U12.4@-2708.71,467.59 -2708.71,433.89 -2690.51,415.69 -2580.51,415.69 -2550.1,446.1 -2550.1,506.42 -2529.88,526.64 U11.3@-2511.71,526.64
LED_SDO_12: U12.3 U13.4 | length 319.5
  Top Layer w6: U13.4@-2905.56,467.59 -2905.56,433.89 -2887.36,415.69 -2777.36,415.69 -2746.95,446.1 -2746.95,506.42 -2726.73,526.64 U12.3@-2708.56,526.64
LED_SDO_13: U13.3 U14.4 | length 319.5
  Top Layer w6: U14.4@-3102.41,467.59 -3102.41,433.89 -3084.21,415.69 -2974.21,415.69 -2943.8,446.1 -2943.8,506.42 -2923.58,526.64 U13.3@-2905.41,526.64
LED_SDO_14: U14.3 U15.4 | length 319.5
  Top Layer w6: U15.4@-3299.2,467.59 -3299.2,433.89 -3281.01,415.69 -3171.01,415.69 -3140.6,446.1 -3140.6,506.42 -3120.38,526.64 U14.3@-3102.2,526.64
LED_SDO_15: U15.3 U16.4 | length 319.5
  Top Layer w6: U16.4@-3496.2,467.59 -3496.2,433.89 -3478.01,415.69 -3368.01,415.69 -3337.6,446.1 -3337.6,506.42 -3317.38,526.64 U15.3@-3299.2,526.64
LED_SDO_16: U16.3 U17.4 | length 319.5
  Top Layer w6: U17.4@-3692.96,467.59 -3692.96,433.89 -3674.76,415.69 -3564.76,415.69 -3534.35,446.1 -3534.35,506.42 -3514.13,526.64 U16.3@-3495.96,526.64
LED_SDO_17: U17.3 U18.4 | length 319.5
  Top Layer w6: U18.4@-3889.81,467.59 -3889.81,433.89 -3871.61,415.69 -3761.61,415.69 -3731.2,446.1 -3731.2,506.42 -3710.98,526.64 U17.3@-3692.81,526.64
LED_SDO_18: U18.3 U19.4 | length 319.5
  Top Layer w6: U19.4@-4086.66,467.59 -4086.66,433.89 -4068.46,415.69 -3958.46,415.69 -3928.05,446.1 -3928.05,506.42 -3907.83,526.64 U18.3@-3889.66,526.64
LED_SDO_19: U19.3 U20.4 | length 319.5
  Top Layer w6: U20.4@-4283.51,467.59 -4283.51,433.89 -4265.31,415.69 -4155.31,415.69 -4124.91,446.1 -4124.91,506.42 -4104.68,526.64 U19.3@-4086.51,526.64
LED_SDO_20: U20.3 U21.4 | length 319.5
  Top Layer w6: U21.4@-4480.36,467.59 -4480.36,433.89 -4462.16,415.69 -4352.16,415.69 -4321.76,446.1 -4321.76,506.42 -4301.53,526.64 U20.3@-4283.36,526.64
LED_SDO_21: U21.3 U22.4 | length 319.5
  Top Layer w6: U22.4@-4677.21,467.59 -4677.21,433.89 -4659.01,415.69 -4549.01,415.69 -4518.61,446.1 -4518.61,506.42 -4498.39,526.64 U21.3@-4480.21,526.64
LED_SDO_22: U22.3 U23.4 | length 319.5
  Top Layer w6: U23.4@-4874.06,467.59 -4874.06,433.89 -4855.86,415.69 -4745.86,415.69 -4715.46,446.1 -4715.46,506.42 -4695.24,526.64 U22.3@-4677.06,526.64
LED_SDO_23: U23.3 U24.4 | length 319.5
  Top Layer w6: U24.4@-5070.91,467.59 -5070.91,433.89 -5052.72,415.69 -4942.72,415.69 -4912.31,446.1 -4912.31,506.42 -4892.09,526.64 U23.3@-4873.91,526.64
LED_SDO_24: U24.2 U25.5 | length 342.6
  Top Layer w6: U25.5 -5235.17,439.68 -5224.18,428.69 -5143.57,428.69 -5121.16,451.1 -5121.16,523.1 -5090.55,553.7 -5053.58,553.7 -5035.33,535.45 U24.2@-5035.33,528.95
LED_SDO_25: U25.3 U26.4 | length 319.5
  Top Layer w6: U26.4@-5464.61,467.59 -5464.61,433.89 -5446.42,415.69 -5336.42,415.69 -5306.01,446.1 -5306.01,506.42 -5285.79,526.64 U25.3@-5267.61,526.64
LED_SDO_26: U26.3 U27.4 | length 319.5
  Top Layer w6: U27.4@-5661.46,467.59 -5661.46,433.89 -5643.27,415.69 -5533.27,415.69 -5502.86,446.1 -5502.86,506.42 -5482.64,526.64 U26.3@-5464.46,526.64
LED_SDO_27: U27.3 U28.4 | length 319.5
  Top Layer w6: U28.4@-5858.31,467.59 -5858.31,433.89 -5840.12,415.69 -5730.12,415.69 -5699.71,446.1 -5699.71,506.42 -5679.49,526.64 U27.3@-5661.31,526.64
LED_SDO_28: U28.3 U29.4 | length 319.5
  Top Layer w6: U29.4@-6055.16,467.59 -6055.16,433.89 -6036.97,415.69 -5926.97,415.69 -5896.56,446.1 -5896.56,506.42 -5876.34,526.64 U28.3@-5858.16,526.64
pads on no net: U29.2 U29.3

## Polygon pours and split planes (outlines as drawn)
GND on Bottom Layer "gnd_bot" (hatched 45Degree grid 30 track 9.5, remove dead copper, pour order 0): -6139.76,401 -6139.76,597.85 73.39,597.85 cw(c73.39,572.81) 98.43,572.81 98.43,-217.11 0,-217.11 0,381.31 ccw(c-19.69,381.31) -19.69,401
+5V on Top Layer (hatched 45Degree grid 30 track 9.5, remove dead copper, pour order 1): -6139.76,401 -6139.76,597.85 73.39,597.85 cw(c73.39,572.81) 98.43,572.81 98.43,-217.11 0,-217.11 0,381.31 ccw(c-19.69,381.31) -19.69,401

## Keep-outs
Keep-Out Layer:
  lines w5: -19.69,401 cw(c-19.69,381.31) 0,381.31 0,-217.11 98.43,-217.11 98.43,572.81 ccw(c73.39,572.81) 73.39,597.85 0,597.85 -334.65,597.85 -6139.76,597.85 -6139.76,401 -19.69,401 ; -19.69,401 -19.69,401

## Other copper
Top Layer:
  pour cut-out: -6080.11,553.7 -6079.81,554 -5954.81,554 -5954.81,440 -5955.13,439.68 -6079.81,439.68 -6079.81,553.4
  pour cut-out: -5292.71,553.7 -5292.41,554 -5167.41,554 -5167.41,440 -5167.73,439.68 -5292.41,439.68 -5292.41,553.4
  pour cut-out: -5489.71,553.7 -5489.41,554 -5364.41,554 -5364.41,440 -5364.73,439.68 -5489.41,439.68 -5489.41,553.4
  pour cut-out: -5883.26,553.7 -5882.96,554 -5757.96,554 -5757.96,440 -5758.28,439.68 -5882.96,439.68 -5882.96,553.4
  pour cut-out: -5686.26,553.7 -5685.96,554 -5560.96,554 -5560.96,440 -5561.28,439.68 -5685.96,439.68 -5685.96,553.4
  pour cut-out: -4505.31,553.7 -4505.01,554 -4380.01,554 -4380.01,440 -4380.32,439.68 -4505.01,439.68 -4505.01,553.4
  pour cut-out: -4702.31,553.7 -4702.01,554 -4577.01,554 -4577.01,440 -4577.32,439.68 -4702.01,439.68 -4702.01,553.4
  pour cut-out: -5095.86,553.7 -5095.56,554 -4970.56,554 -4970.56,440 -4970.88,439.68 -5095.56,439.68 -5095.56,553.4
  pour cut-out: -4898.86,553.7 -4898.56,554 -4773.56,554 -4773.56,440 -4773.88,439.68 -4898.56,439.68 -4898.56,553.4
  pour cut-out: -3717.91,553.7 -3717.61,554 -3592.61,554 -3592.61,440 -3592.92,439.68 -3717.61,439.68 -3717.61,553.4
  pour cut-out: -3914.91,553.7 -3914.61,554 -3789.61,554 -3789.61,440 -3789.92,439.68 -3914.61,439.68 -3914.61,553.4
  pour cut-out: -4308.46,553.7 -4308.16,554 -4183.16,554 -4183.16,440 -4183.47,439.68 -4308.16,439.68 -4308.16,553.4
  pour cut-out: -4111.46,553.7 -4111.16,554 -3986.16,554 -3986.16,440 -3986.47,439.68 -4111.16,439.68 -4111.16,553.4
  pour cut-out: -2930.5,553.7 -2930.2,554 -2805.2,554 -2805.2,440 -2805.52,439.68 -2930.2,439.68 -2930.2,553.4
  pour cut-out: -3127.5,553.7 -3127.2,554 -3002.2,554 -3002.2,440 -3002.52,439.68 -3127.2,439.68 -3127.2,553.4
  pour cut-out: -3521.05,553.7 -3520.76,554 -3395.76,554 -3395.76,440 -3396.07,439.68 -3520.76,439.68 -3520.76,553.4
  pour cut-out: -3324.05,553.7 -3323.76,554 -3198.76,554 -3198.76,440 -3199.07,439.68 -3323.76,439.68 -3323.76,553.4
  pour cut-out: -2143.1,553.7 -2142.8,554 -2017.8,554 -2017.8,440 -2018.12,439.68 -2142.8,439.68 -2142.8,553.4
  pour cut-out: -2340.1,553.7 -2339.8,554 -2214.8,554 -2214.8,440 -2215.12,439.68 -2339.8,439.68 -2339.8,553.4
  pour cut-out: -2733.65,553.7 -2733.35,554 -2608.35,554 -2608.35,440 -2608.67,439.68 -2733.35,439.68 -2733.35,553.4
  pour cut-out: -2536.65,553.7 -2536.35,554 -2411.35,554 -2411.35,440 -2411.67,439.68 -2536.35,439.68 -2536.35,553.4
  pour cut-out: -1355.7,553.7 -1355.4,554 -1230.4,554 -1230.4,440 -1230.72,439.68 -1355.4,439.68 -1355.4,553.4
  pour cut-out: -1552.7,553.7 -1552.4,554 -1427.4,554 -1427.4,440 -1427.72,439.68 -1552.4,439.68 -1552.4,553.4
  pour cut-out: -1946.25,553.7 -1945.95,554 -1820.95,554 -1820.95,440 -1821.27,439.68 -1945.95,439.68 -1945.95,553.4
  pour cut-out: -1749.25,553.7 -1748.95,554 -1623.95,554 -1623.95,440 -1624.27,439.68 -1748.95,439.68 -1748.95,553.4
  pour cut-out: -961.85,553.7 -961.55,554 -836.55,554 -836.55,440 -836.87,439.68 -961.55,439.68 -961.55,553.4
  pour cut-out: -1158.85,553.7 -1158.55,554 -1033.55,554 -1033.55,440 -1033.87,439.68 -1158.55,439.68 -1158.55,553.4
  pour cut-out: -765.3,553.7 -765,554 -640,554 -640,440 -640.32,439.68 -765,439.68 -765,553.4
  pour cut-out: -568.3,553.7 -568,554 -443,554 -443,440 -443.32,439.68 -568,439.68 -568,553.4

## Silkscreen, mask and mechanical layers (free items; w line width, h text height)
Mechanical 1:
  lines w5: -6138.76,499 cw(c-6138.34,499) -6138.34,499.43 -334.65,499.43 -334.65,597.85 ; -6022.58,489.93 -6022.58,508.93 ; -5825.72,489.93 -5825.72,508.93 ; -5628.87,489.93 -5628.87,508.93 ; -5432.02,489.93 -5432.02,508.93 ; -5235.17,489.93 -5235.17,508.93 ; -5038.32,489.93 -5038.32,508.93 ; -4841.47,489.93 -4841.47,508.93 ; -4644.62,489.93 -4644.62,508.93 ; -4447.77,489.93 -4447.77,508.93 ; -4250.92,489.93 -4250.92,508.93 ; -4054.07,489.93 -4054.07,508.93 ; -3857.22,489.93 -3857.22,508.93 ; -3660.37,489.93 -3660.37,508.93 ; -3463.52,489.93 -3463.52,508.93 ; -3266.67,489.93 -3266.67,508.93 ; -3069.82,489.93 -3069.82,508.93 ; -2872.97,489.93 -2872.97,508.93 ; -2676.12,489.93 -2676.12,508.93 ; -2479.27,489.93 -2479.27,508.93 ; -2282.42,489.93 -2282.42,508.93 ; -2085.57,489.93 -2085.57,508.93 ; -1888.72,489.93 -1888.72,508.93 ; -1691.87,489.93 -1691.87,508.93 ; -1495.02,489.93 -1495.02,508.93 ; -1298.17,489.93 -1298.17,508.93 ; -1101.32,489.93 -1101.32,508.93 ; -904.46,489.93 -904.46,508.93 ; -707.61,489.93 -707.61,508.93 ; -162.71,58.48 98.43,58.48 ; 0,546 0,597.85 ; -510.76,489.93 -510.76,508.93 ; -510.76,489.93 -510.76,508.93 ; -510.76,489.93 -510.76,508.93 ; -510.76,489.93 -510.76,508.93
Mechanical 4:
  lines w5: -19.69,401 cw(c-19.69,381.31) 0,381.31 0,-217.11 98.43,-217.11 98.43,572.81 ccw(c73.39,572.81) 73.39,597.85 0,597.85 -334.65,597.85 -6139.76,597.85 -6139.76,401 -19.69,401 ; -19.69,401 -19.69,401
Drill Drawing:
  text "PWB, LED STRIP FLEX" at 1137.71,-3973.31 h157.48
  text "PWB-020218-001" at 1324.71,-4299.1 h127.95
  text "1" at 3749.91,-4358.15 h78.74
  text "1" at 3560.93,-4362.09 h78.74
Mechanical 17:
  text "PWB, LED STRIP FLEX" at 1180.33,-4047.9 h157.48
  text "PWA-020218-001" at 1374.33,-4338.9 h127.95
  text "1" at 3553.06,-4350.28 h59.06
  text "1" at 3742.04,-4350.28 h59.06
  text "NOTES: /  / 1. ALL ASSEMBLY MATERIALS TO BE RoHS COMPLIANT. /  / 2. MATERIAL: /           • FLEXIBLE METAL CLAD DIELECTRIC IAW                 /             IPC-4204/11 E1E2 O0/0 CU W7 T/T /           • STIFFENER IAW IPC-4203/1-E1E8M1 /  / 3. FINISH:  IMMERSION GOLD /  / ALL EXPOSED CONDUCTIVE PATTERN AREAS NOT COVERED WITH COVERLAY MATERIAL OR OTHER PLATING  / SHALL BE IMMERSION GOLD (0.000030-0.000090 mm) OVER ELECTROLESS NICKEL (0.001-0.006 mm). /  / 4. LEGEND SHALL BE WHITE, PERMANENT, ORGANIC, NON-CONDUCTIVE UV OR EPOXY TYPE INK APPLIED  / TO THE TOP SIDE OF THE BOARD. THERE SHALL BE NO LEGEND ON ANY SOLDERABLE COMPONENT LAND. /  / 5. ALL ASSEMBLY MATERIALS TO BE RoHS COMPLIANT. /  / 6. ANY LABELS OR COMPOSITION OF, APPLIED TO THE BOARD NEED TO BE APPROVIED BY AIRZAI /  / 7. MINIMUM TRACE WIDTHS: /           EXTERNAL: 0.203 mm  INTERNAL: N/A /  / 8. MINIMUM SPACE BETWEEN FEATURES: /          EXTERNAL: 0.15 mm  INTERNAL: N/A /  / 9. Overall Board Thickness: 0.3mm" at -10133.76,-4446 h78.74
Mechanical 18:
  lines w5: -10554.62,-2216.22 -10354.62,-2216.22 ; -10554.62,158.78 -10354.62,158.78 ; -10554.62,2533.78 -10354.62,2533.78 ; -8054.62,-4591.22 -8054.62,-4391.22 ; -8054.62,4708.78 -8054.62,4908.78 ; -5554.62,-4591.22 -5554.62,-4391.22 ; -5554.62,4708.78 -5554.62,4908.78 ; -3054.62,-4591.22 -3054.62,-4391.22 ; -3054.62,4708.78 -3054.62,4908.78 ; -554.62,-4591.22 -554.62,-4391.22 ; -554.62,4708.78 -554.62,4908.78 ; -255.41,-4093.44 4244.59,-4093.44 ; -255.41,-3851.7 815.25,-3851.7 ; -255.41,-3617.65 815.25,-3617.65 ; -255.41,-3406.82 815.25,-3406.82 ; -254.62,-4391.22 4245.38,-4391.22 ; 370.37,-4394.42 370.37,-3194.42 ; 815.25,-4393.44 815.25,-3193.44 ; 815.25,-3726.51 4244.44,-3726.51 ; 1155.22,-3193.44 4244.59,-3193.44 ; 1244.59,-3193.44 -255.41,-3193.44 ; 1945.38,-4591.22 1945.38,-4391.22 ; 1945.38,4708.78 1945.38,4908.78 ; 3868.21,-4393.44 3868.21,-4093.44 ; 4245.38,-3191.22 4245.38,-4391.22 ; 4245.38,-2216.22 4445.38,-2216.22 ; 4245.38,2533.78 4445.38,2533.78 ; -1655.41,-4393.44 -255.41,-4393.44 ; -1655.41,-4393.44 -255.41,-4393.44 ; -1655.41,-4393.44 -1655.41,-3193.44 -255.41,-3193.44 ; -255.41,-4393.44 4244.59,-4393.44 ; -255.41,-4393.44 4244.59,-4393.44 ; -255.41,-4393.44 -255.41,-3193.44 ; 4244.59,-4393.44 4244.59,-3193.44 ; 4244.59,-4393.44 4244.59,-3193.44 ; 4245.38,-4391.22 4245.38,4708.78 -10354.62,4708.78 -10354.62,-4391.22 4245.38,-4391.22 ; -10554.62,-4591.22 -10554.62,4908.78 4445.38,4908.78 4445.38,-4591.22 -10554.62,-4591.22
  text "1" at -9323.28,4778.78 h70
  text "2" at -6827.62,4778.78 h70
  text "3" at -4338.28,4778.78 h70
  text "4" at -1831.61,4778.78 h70
  text "5" at 667.38,4778.78 h70
  text "6" at 3172.38,4778.78 h70
  text "A" at -10479.62,3635.78 h70
  text "A" at 4320.38,3635.78 h70
  text "B" at -10479.62,1255.78 h70
  text "B" at 4320.38,1255.78 h70
  text "C" at -10479.62,-1119.22 h70
  text "C" at 4320.38,-1119.22 h70
  text "AIRZAI PROPRIETARY & CONFIDENTIAL" at -99.5,-3082.56 h127.95
  text "DATE:" at 400.88,-3255.64 h45
  text "ENGINEER:" at -232.97,-3261.94 h45
  text "UNLESS OTHERWISE SPECIFIED" at -1555.81,-3322.57 h59.06
  text "21/01/19" at 408.22,-3364.25 h59.06
  text "FD" at -40.1,-3370.52 h78.74
  text "DIMENSIONS ARE IN MM" at -1433.76,-3448.55 h59.06
  text "PCB DESIGNER:" at -236.91,-3470.33 h45
  text "DATE:" at 389.07,-3472.18 h45
  text "D" at -10479.62,-3489.22 h70
  text "D" at 4320.38,-3489.22 h70
  text "AIRZAI" at 1106.21,-3527.44 h127.95
  text "TOLERANCES" at -1232.97,-3574.54 h59.06
  text "21/01/19" at 408.22,-3578.82 h59.06
  text "DFM" at -66.48,-3580.4 h78.74
  text "DATE:" at 389.07,-3684.77 h45
  text "CHECK" at -236.91,-3686.86 h45
  text "ANGULAR" at -748.72,-3732.02 h59.06
  text "DECIMALS" at -1551.87,-3743.83 h59.06
  text "TITLE:" at 867.04,-3790.24 h45
  text "FD" at -0.73,-3803.59 h78.74
  text ".XX +/- .127MM" at -1599.12,-3901.31 h59.06
  text "+/-" at -760.53,-3905.25 h59.06
  text "REL" at -225.1,-3917.85 h45
  text "DATE:" at 404.82,-3924.93 h45
  text "FD" at -10.57,-4020.13 h78.74
  text ".XXX +/- .080MM" at -1610.93,-4062.73 h59.06
  text "REV:" at 3890.65,-4157.22 h45
  text "SCALE:" at 410.33,-4158 h45
  text "DWG NO:" at 861.51,-4165.88 h45
  text "SIZE" at -225.1,-4169.03 h45
  text "B" at -21.36,-4299.62 h120
  text "DO NOT SCALE DRAWING" at -1555.81,-4302.88 h70.87
  text "A" at 3974.32,-4318.78 h120
  text "1:1" at 458.96,-4323.24 h120
  text "SHEET" at 3326.08,-4354.85 h45
  text "OF" at 3589.86,-4354.85 h45
  text "1" at -9323.28,-4521.22 h70
  text "2" at -6827.62,-4521.22 h70
  text "3" at -4338.28,-4521.22 h70
  text "4" at -1831.61,-4521.22 h70
  text "5" at 667.38,-4521.22 h70
  text "6" at 3172.38,-4521.22 h70

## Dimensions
-334.65,723 to 0,597.85 on Mechanical 1
-6139.76,597.85 to -334.65,597.85 on Mechanical 1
